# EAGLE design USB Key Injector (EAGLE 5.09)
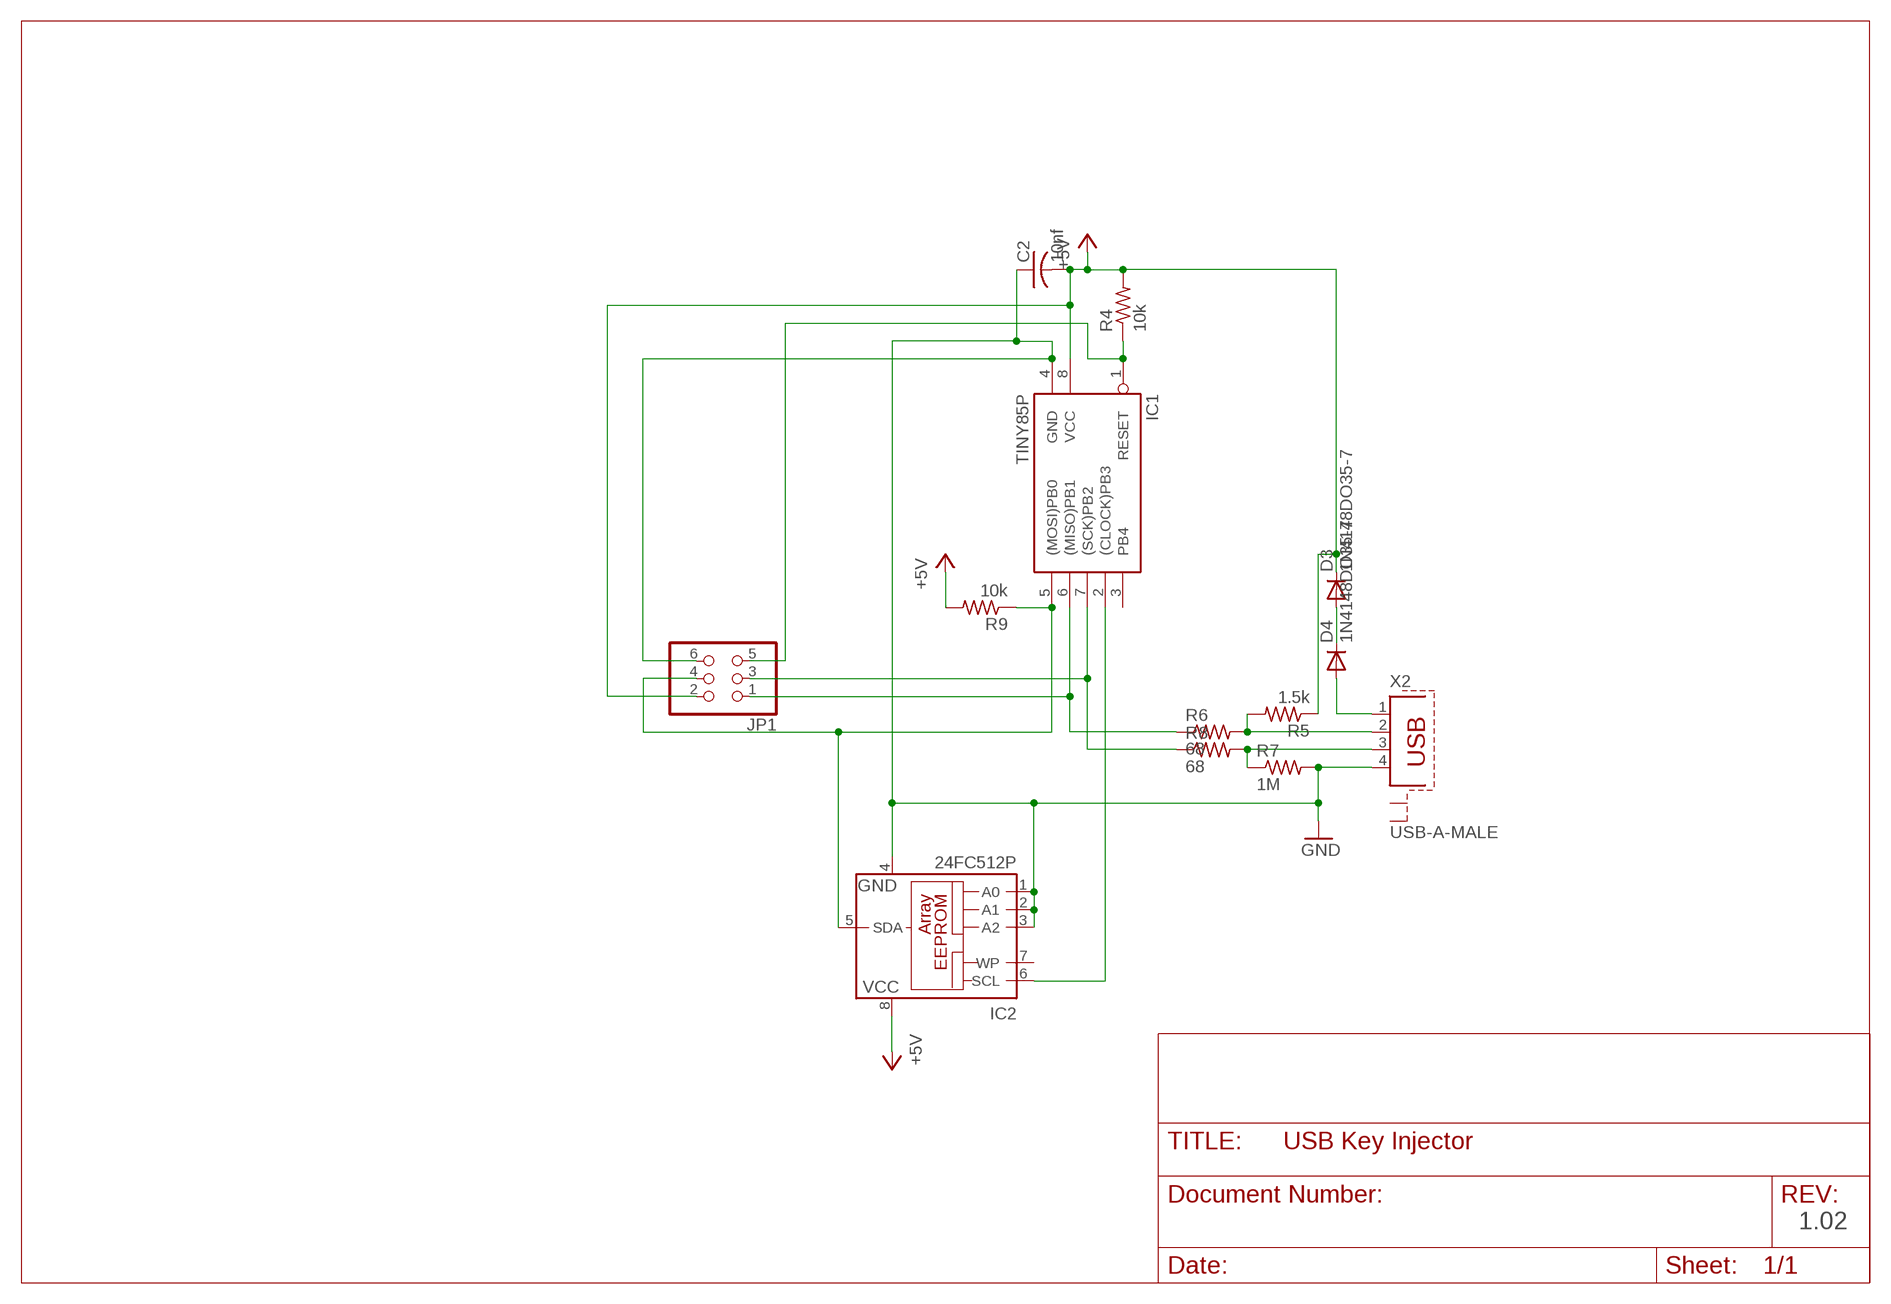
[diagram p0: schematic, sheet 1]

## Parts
C2  10nf  C-US025-025X050  [C025-025X050]
D3  1N4148DO35-7  [DO35-7]
D4  1N4148DO35-7  [DO35-7]
IC1  TINY85P  [DIL08]
IC2  24FC512P  [DIL8]
JP1  PINHD-2X3  [2X03]
R4  10k  R-US_0207/10  [0207/10]
R5  1.5k  R-US_0207/10  [0207/10]
R6  68  R-US_0207/10  [0207/10]
R7  1M  R-US_0207/10  [0207/10]
R8  68  R-US_0207/10  [0207/10]
R9  10k  R-US_0207/10  [0207/10]
X2  USB-A-MALE  [USB-A-HOLES]

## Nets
+5V: C2.2 D3.C IC1.8(VCC) IC2.8(VCC) JP1.2 R4.2 R5.1 R9.2
GND: C2.1 IC1.4(GND) IC2.1(A0) IC2.2(A1) IC2.3(A2) IC2.4(GND) JP1.6 R7.2 X2.4
N$2: IC1.2((CLOCK)PB3) IC2.6(SCL)
N$4: IC1.6((MISO)PB1) JP1.1 R6.1
N$6: IC1.1(RESET) JP1.5 R4.1
N$7: IC1.7((SCK)PB2) JP1.3 R8.1
N$9: R5.2 R6.2 X2.2
N$10: R7.1 R8.2 X2.3
N$11: D4.A X2.1
N$12: D3.A D4.C
N$13: IC1.5((MOSI)PB0) IC2.5(SDA) JP1.4 R9.1
Unconnected: IC1.3(PB4) IC2.7(WP) X2.S1 X2.S2

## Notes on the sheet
- 1.02

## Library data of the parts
C2 = rcl:C-US: CAPACITOR, American symbol
D3 D4 = diode:1N4148: DIODE
IC1 = atmel_custom:TINY85: MICROCONTROLLER 1K ROM 128 bytes RAM 128 bytes EEPROM
IC2 = microchip_custom:24*: Serial EEPROM I2C
JP1 = pinhead:PINHD-2X3: PIN HEADER
R4-R9 = rcl:R-US_: RESISTOR, American symbol
X2 = molex-usb-addl:USB-A-MALE

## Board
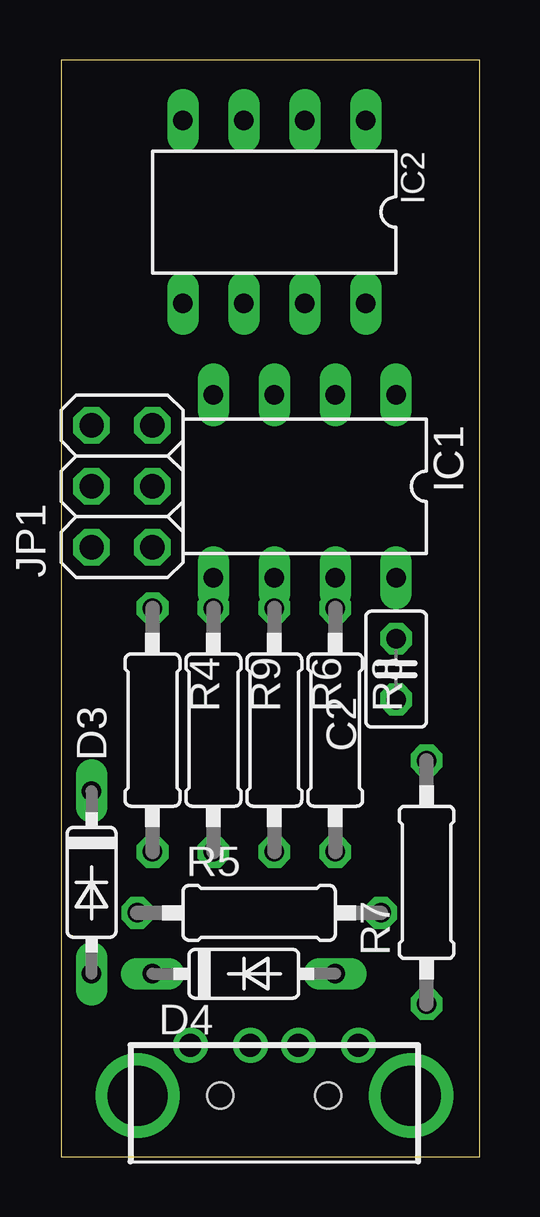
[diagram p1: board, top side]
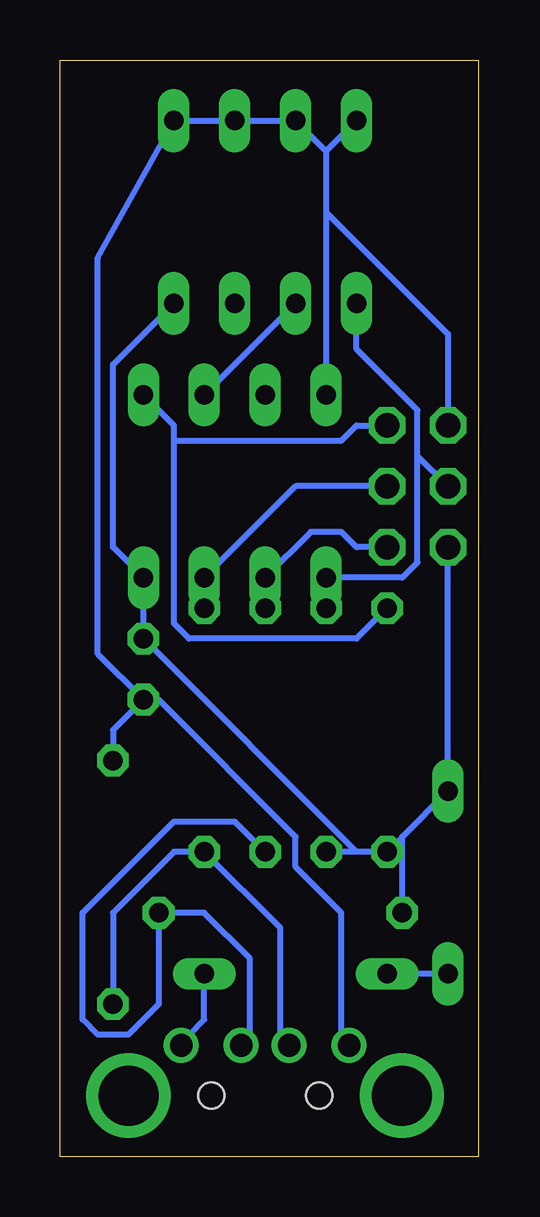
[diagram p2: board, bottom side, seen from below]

Size 17.45 x 45.71 mm. Coordinates in mm from the lower left corner, seen from the top.
Outline: 0,0 17.45,0 17.45,45.71 0,45.71 0,0
Copper layers 16: Bottom 0.035mm
Design rules "1s_laser_spread *": minimum track width 10mil, minimum drill 24mil, track to track 15mil, track to pad 15mil, pad to pad 15mil, via to via 15mil, smd to smd 8mil, copper to edge 15mil, drill to drill 15mil, minimum pad ring 10mil, minimum via ring 8mil, stop-mask expansion 4mil, vias tented up to drill 0mil, thermal gap 10mil

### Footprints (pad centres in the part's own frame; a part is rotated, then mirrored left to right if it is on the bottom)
C025-025X050 = drill 0.813 octagon: 1 -1.27,0; 2 1.27,0
DO35-7 = drill 0.813 long: A 3.81,0; C -3.81,0
DIL08 = drill 0.813 long: 1 -3.81,-3.81; 2 -1.27,-3.81; 3 1.27,-3.81; 4 3.81,-3.81; 5 3.81,3.81; 6 1.27,3.81; 7 -1.27,3.81; 8 -3.81,3.81
DIL8 = drill 0.813 long: 1 -3.81,-3.81; 2 -1.27,-3.81; 3 1.27,-3.81; 4 3.81,-3.81; 5 3.81,3.81; 6 1.27,3.81; 7 -1.27,3.81; 8 -3.81,3.81
2X03 = drill 1.016 octagon: 1 -2.54,-1.27; 2 -2.54,1.27; 3 0,-1.27; 4 0,1.27; 5 2.54,-1.27; 6 2.54,1.27
0207/10 = drill 0.813 octagon: 1 -5.08,0; 2 5.08,0
USB-A-HOLES = drill 0.95 round: 1 3.5,2.1; 2 1,2.1; 3 -1,2.1; 4 -3.5,2.1 | drill 2.5 pad 3 round: S1 5.7,0; S2 -5.7,0 | hole 1.1: -2.25,0; 2.25,0

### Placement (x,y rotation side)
C2  13.97,20.32 90 top
D3  1.27,11.43 270 top
D4  7.62,7.62 0 top
IC1  10.16,27.94 180 top
IC2  8.89,39.37 180 top
JP1  2.54,27.94 90 top
R4  3.81,17.78 270 top
R5  8.26,10.16 0 top
R6  8.89,17.78 270 top
R7  15.24,11.43 90 top
R8  11.43,17.78 270 top
R9  6.35,17.78 270 top
X2  8.89,2.54 0 top

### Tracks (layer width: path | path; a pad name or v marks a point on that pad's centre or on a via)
+5V
  Bottom 0.254: IC2.8 15.24,33.02 15.24,25.4 IC1.8 C2.2 5.08,12.7 | 3.17,13.34 R4.2 5.08,12.7 | 3.17,13.34 D3.C JP1.2 | R5.1 3.17,13.34 | 5.08,12.7 R9.2
GND
  Bottom 0.254: R7.2 15.24,17.78 C2.1 | C2.1 13.34,19.05 7.62,13.34 7.62,12.06 5.71,10.16 5.71,5.08 X2.4 | 6.35,41.91 6.35,39.37 | 6.35,39.37 IC1.4 | 6.35,41.91 IC2.4 | 6.35,41.91 IC2.3 IC2.2 IC2.1 15.88,37.47 15.88,20.95 C2.1 | JP1.6 1.27,34.29 6.35,39.37
N$2
  Bottom 0.254: IC1.2 IC2.6
N$4
  Bottom 0.254: R6.1 IC1.6 6.99,26.04 5.71,26.04 5.08,25.4 JP1.1
N$6
  Bottom 0.254: R4.1 5.08,21.59 12.06,21.59 12.7,22.23 12.7,29.84 | 12.7,29.84 12.7,30.48 IC1.1 | JP1.5 5.08,30.48 5.71,29.84 12.7,29.84
N$7
  Bottom 0.254: R8.1 IC1.7 7.62,27.94 JP1.3
N$9
  Bottom 0.254: X2.2 9.53,5.08 9.53,8.26 11.43,10.16 R5.2 13.34,6.35 14.61,5.08 15.88,5.08 16.51,5.71 16.51,10.16 12.7,13.97 10.16,13.97 R6.2
N$10
  Bottom 0.254: R7.1 15.24,10.16 12.7,12.7 R8.2 8.26,9.53 8.26,5.08 X2.3
N$11
  Bottom 0.254: D4.A 11.43,5.71 12.06,5.08 X2.1
N$12
  Bottom 0.254: D3.A D4.C
N$13
  Bottom 0.254: R9.1 IC1.5 3.17,24.13 2.54,24.77 2.54,29.21 | IC2.5 5.08,33.66 2.54,31.11 2.54,29.21 | 2.54,29.21 JP1.4

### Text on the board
tValues: UKI v1.02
